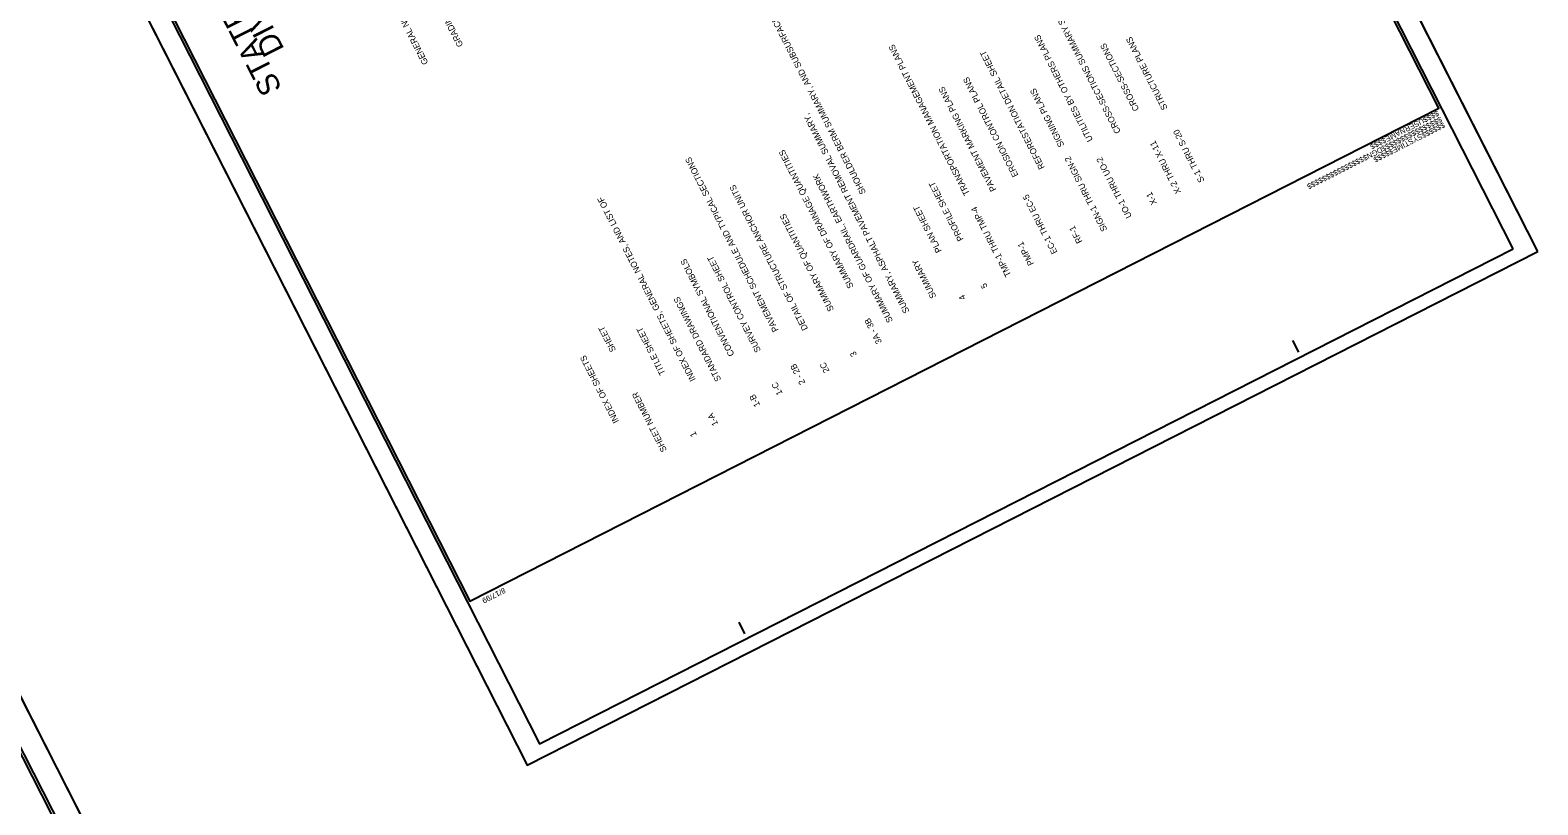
# Model space of a CAD drawing. Extents: x 558484 to 564063, y 513718 to 518374.
# Drawn here: x 562607 to 564063, y 516339 to 517087 of the extents above; entities that cross this region are included whole.
import ezdxf

# ---------------------------------------------------------------- set-up
doc = ezdxf.new("R2010")
doc.units = 0
for name, color, linetype in [('Default', 7, 'Continuous'), ('Sheet Cutting Line CELL', 7, 'Continuous'), ('Sheet Data Text CELL', 7, 'Continuous'), ('Sheet Plan CELL', 7, 'Continuous'), ('Sheet Plot Border Inside CELL', 7, 'Continuous'), ('Sheet Plot Border Outside CELL', 7, 'Continuous'), ('Sheet Summary CELL', 7, 'Continuous'), ('Sheet Symbology CELL', 7, 'Continuous')]:
    doc.layers.add(name, color=color, linetype=linetype)

msp = doc.modelspace()

# ---------------------------------------------------------------- linework, layer by layer
at = {"layer": 'Sheet Cutting Line CELL'}
for p, q in [((564062.7, 516873.6), (563299.7, 518374.3)), ((562323.6, 517878), (563086.6, 516377.3)), ((562761.8, 516121), (561997.8, 517621.7)), ((563086.6, 516377.3), (564062.7, 516873.6))]:
    msp.add_line(p, q, dxfattribs=at)
at = {"layer": 'Sheet Plan CELL'}
for p, q in [((563967.2, 517011.8), (563967.2, 517011.8)), ((563831.7, 516776.3), (563826, 516787.5)), ((563031.2, 516535.9), (563031.2, 516535.9)), ((563296.8, 516504.4), (563291.2, 516515.5))]:
    msp.add_line(p, q, dxfattribs=at)
msp.add_lwpolyline([(562351.4, 517873), (563031.2, 516535.9), (563967.2, 517011.8), (563287.3, 518348.9)], close=True, dxfattribs=at)
at = {"layer": 'Sheet Plot Border Inside CELL'}
for points in [[(564039, 516876.1), (563283.9, 518361.2), (562343.5, 517883), (563098.5, 516398)], [(561039.6, 517128.8), (561795.7, 515643.7), (562735.9, 516122.4), (561979.8, 517607.5)]]:
    msp.add_lwpolyline(points, close=True, dxfattribs=at)
at = {"layer": 'Sheet Plot Border Outside CELL'}
for points in [[(564062.7, 516873.6), (563299.7, 518374.3), (562323.6, 517878), (563086.6, 516377.3)], [(561017.5, 517122.6), (561781.6, 515621.9), (562761.8, 516121), (561997.8, 517621.7)]]:
    msp.add_lwpolyline(points, close=True, dxfattribs=at)
at = {"layer": 'Sheet Summary CELL'}
msp.add_lwpolyline([(561047.5, 517118.8), (561728.1, 515782.1), (562663.8, 516258.4), (561983.2, 517595.2)], close=True, dxfattribs=at)

# ---------------------------------------------------------------- texts
at = {"layer": 'Default'}
for s, p in [('GRADING AND SURFACING OR RESURFACING AND WIDENING:  ', (563025, 517072.8)), ('GENERAL NOTES:                         2012 SPECIFICATIONS', (562991.3, 517055.7))]:
    msp.add_text(s, height=6, rotation=117.0942, dxfattribs=at).set_placement(p)
at = {"layer": 'Sheet Data Text CELL'}
for s, p in [('SHOULDER BERM SUMMARY, AND SUBSURFACE DRAINAGE', (563413.9, 516930.5)), ('X-1                             CROSS-SECTIONS SUMMARY SHEETS', (563695, 516920.4)), ('UO-1 THRU UO-2        UTILITIES BY OTHERS PLANS', (563670.8, 516907.4)), ('S-1 THRU S-20          STRUCTURE PLANS', (563740.9, 516942)), ('TMP-1 THRU TMP-4      TRANSPORTATION MANAGEMENT PLANS', (563554.2, 516850.8)), ('RF-1                            REFORESTATION DETAIL SHEET', (563623, 516883.1)), ('X-2 THRU X-11               CROSS-SECTIONS', (563718.4, 516931)), ('EC-1 THRU EC-5         EROSION CONTROL PLANS', (563598.9, 516872.9)), ('PMP-1                         PAVEMENT MARKING PLANS', (563576.2, 516861.7)), ('SIGN-1 THRU SIGN-2     SIGNING PLANS', (563647, 516894.6)), ('                                SUMMARY, ASPHALT PAVEMENT REMOVAL SUMMARY,', (563488.3, 516752)), ('2 - 2B                PAVEMENT SCHEDULE AND TYPICAL SECTIONS', (563355.4, 516746.7)), ('3A - 3B               SUMMARY OF DRAINAGE QUANTITIES ', (563429.4, 516786)), ('                                SUMMARY OF GUARDRAIL, EARTHWORK ', (563472.3, 516743)), ('2C                DETAIL OF STRUCTURE ANCHOR UNITS', (563378.8, 516758.1)), ('5                     PROFILE SHEET  ', (563531.5, 516839.6)), ('1-A                INDEX OF SHEETS, GENERAL NOTES, AND LIST OF ', (563271.4, 516706.9)), ('3                    SUMMARY OF QUANTITIES ', (563405.3, 516773.7)), ('4                     PLAN SHEET', (563510.4, 516828.4)), ('1-B                   CONVENTIONAL SYMBOLS ', (563311.8, 516725.2)), ('1-C               SURVEY CONTROL SHEET', (563333.5, 516736.5)), ('                                SUMMARY ', (563514.2, 516766.4)), ('                STANDARD DRAWINGS', (563290.3, 516718)), ('SHEET NUMBER                    SHEET   ', (563221.7, 516681.7)), ('1                            TITLE SHEET', (563250.6, 516696.3)), ('                        INDEX OF SHEETS ', (563199.7, 516661.8))]:
    msp.add_text(s, height=6, rotation=116.9503, dxfattribs=at).set_placement(p)
at = {"layer": 'Sheet Plan CELL'}
for s, p in [('$$$$USERNAME$$$$', (563965.5, 517009.8)), ('$$$$$$$$$$$$$$$$DGN$$$$$$$$$$$$$$$$', (563968.5, 517003.9)), ('$$$$$$SYSTIME$$$$$', (563971.3, 516998.5)), ('8/17/99', (563064, 516549))]:
    msp.add_text(s, height=5.25, rotation=206.9503, dxfattribs=at).set_placement(p)
at = {"layer": 'Sheet Symbology CELL'}
for s, p in [('STATE OF NORTH CAROLINA', (562850.2, 517030.9)), ('DIVISION OF HIGHWAYS', (562852.4, 517068.9))]:
    msp.add_text(s, height=21.419, rotation=116.9503, dxfattribs=at).set_placement(p)

doc.saveas('drawing.dxf')
